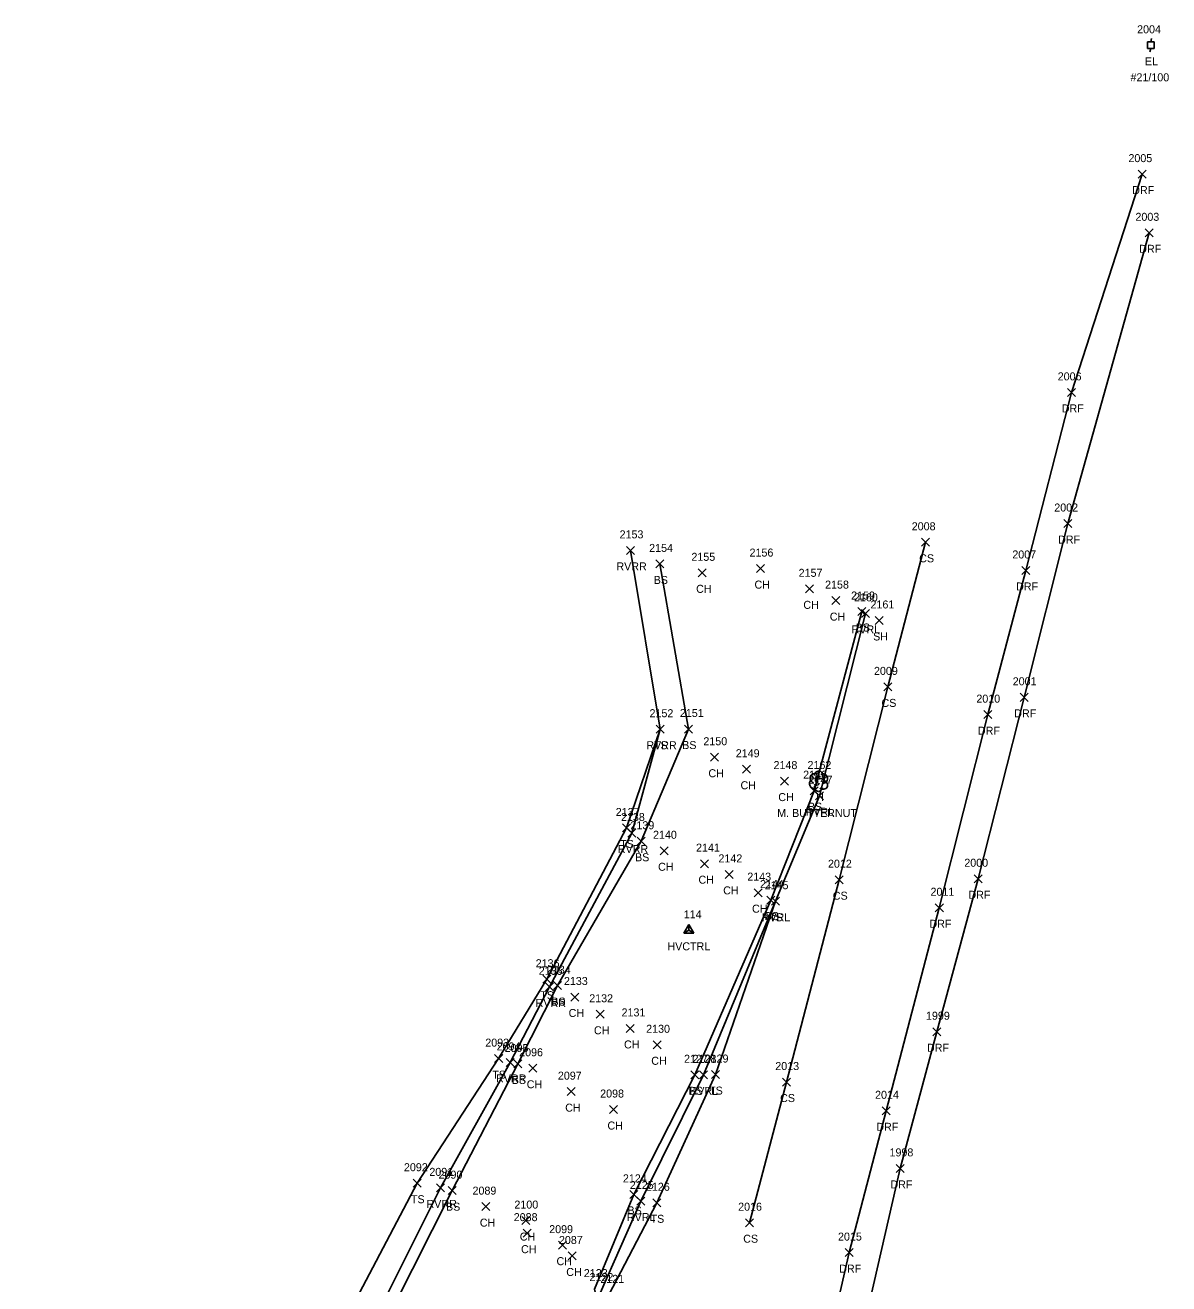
# Model space of a CAD drawing. Extents: x 1600395 to 1603269, y 874955 to 877143.
# Drawn here: x 1601782.9 to 1602068.5, y 875406.7 to 875721.2 of the extents above; entities that cross this region are included whole.
import ezdxf

# ---------------------------------------------------------------- set-up
doc = ezdxf.new("R2010")
doc.units = 0
for name, color, linetype in [('C_A', 7, 'Continuous'), ('C_I', 7, 'Continuous'), ('CPSM', 7, 'Continuous'), ('L_A', 7, 'Continuous'), ('L_C', 7, 'Continuous'), ('L_I', 7, 'Continuous'), ('L_TIC', 7, 'Continuous'), ('LAWE', 7, 'Continuous'), ('LELB', 7, 'Continuous'), ('LTD', 7, 'Continuous'), ('R_A', 7, 'Continuous'), ('R_I', 7, 'Continuous'), ('R_TIC', 7, 'Continuous'), ('RDF', 7, 'Continuous'), ('U_A', 7, 'Continuous'), ('U_C', 7, 'Continuous'), ('U_I', 7, 'Continuous'), ('UEPT', 7, 'Continuous')]:
    doc.layers.add(name, color=color, linetype=linetype)

msp = doc.modelspace()

# ---------------------------------------------------------------- linework, layer by layer
at = {"layer": 'CPSM'}
for p, q in [((1601947.35, 875494.34), (1601948.6, 875496.51)), ((1601949.85, 875494.34), (1601948.6, 875496.51)), ((1601948.6, 875495.06), (1601948.6, 875496.51)), ((1601947.35, 875494.34), (1601948.6, 875495.06)), ((1601947.35, 875494.34), (1601949.85, 875494.34)), ((1601948.6, 875495.06), (1601948.6, 875495.06)), ((1601948.6, 875495.06), (1601949.85, 875494.34))]:
    msp.add_line(p, q, dxfattribs=at)
at = {"layer": 'L_TIC'}
for points in [[(1601933.04, 875589), (1601935.04, 875591)], [(1601935.04, 875589), (1601933.04, 875591)], [(1602006.73, 875591.02), (1602008.73, 875593.02)], [(1602008.73, 875591.02), (1602006.73, 875593.02)], [(1601940.42, 875585.61), (1601942.42, 875587.61)], [(1601942.42, 875585.61), (1601940.42, 875587.61)], [(1601950.97, 875583.39), (1601952.97, 875585.39)], [(1601952.97, 875583.39), (1601950.97, 875585.39)], [(1601965.55, 875584.45), (1601967.55, 875586.45)], [(1601967.55, 875584.45), (1601965.55, 875586.45)], [(1601977.75, 875579.39), (1601979.75, 875581.39)], [(1601979.75, 875579.39), (1601977.75, 875581.39)], [(1601984.36, 875576.45), (1601986.36, 875578.45)], [(1601986.36, 875576.45), (1601984.36, 875578.45)], [(1601990.87, 875573.72), (1601992.87, 875575.72)], [(1601992.87, 875573.72), (1601990.87, 875575.72)], [(1601991.72, 875573.26), (1601993.72, 875575.26)], [(1601993.72, 875573.26), (1601991.72, 875575.26)], [(1601995.18, 875571.49), (1601997.18, 875573.49)], [(1601997.18, 875571.49), (1601995.18, 875573.49)], [(1601997.31, 875554.89), (1601999.31, 875556.89)], [(1601999.31, 875554.89), (1601997.31, 875556.89)], [(1601940.51, 875544.31), (1601942.51, 875546.31)], [(1601942.51, 875544.31), (1601940.51, 875546.31)], [(1601940.51, 875544.31), (1601942.51, 875546.31)], [(1601942.51, 875544.31), (1601940.51, 875546.31)], [(1601947.53, 875544.36), (1601949.53, 875546.36)], [(1601949.53, 875544.36), (1601947.53, 875546.36)], [(1601954.05, 875537.31), (1601956.05, 875539.31)], [(1601956.05, 875537.31), (1601954.05, 875539.31)], [(1601962.06, 875534.31), (1601964.06, 875536.31)], [(1601964.06, 875534.31), (1601962.06, 875536.31)], [(1601971.49, 875531.35), (1601973.49, 875533.35)], [(1601973.49, 875531.35), (1601971.49, 875533.35)], [(1601978.94, 875528.95), (1601980.94, 875530.95)], [(1601980.94, 875528.95), (1601978.94, 875530.95)], [(1601980.24, 875527.67), (1601982.24, 875529.67)], [(1601982.24, 875527.67), (1601980.24, 875529.67)], [(1601932.08, 875519.64), (1601934.08, 875521.64)], [(1601934.08, 875519.64), (1601932.08, 875521.64)], [(1601933.38, 875518.38), (1601935.38, 875520.38)], [(1601935.38, 875518.38), (1601933.38, 875520.38)], [(1601935.76, 875516.32), (1601937.76, 875518.32)], [(1601937.76, 875516.32), (1601935.76, 875518.32)], [(1601941.47, 875513.94), (1601943.47, 875515.94)], [(1601943.47, 875513.94), (1601941.47, 875515.94)], [(1601951.56, 875510.71), (1601953.56, 875512.71)], [(1601953.56, 875510.71), (1601951.56, 875512.71)], [(1601957.73, 875508.04), (1601959.73, 875510.04)], [(1601959.73, 875508.04), (1601957.73, 875510.04)], [(1601985.16, 875506.71), (1601987.16, 875508.71)], [(1601987.16, 875506.71), (1601985.16, 875508.71)], [(1601964.93, 875503.47), (1601966.93, 875505.47)], [(1601966.93, 875503.47), (1601964.93, 875505.47)], [(1601968.1, 875501.62), (1601970.1, 875503.62)], [(1601970.1, 875501.62), (1601968.1, 875503.62)], [(1601969.27, 875501.33), (1601971.27, 875503.33)], [(1601971.27, 875501.33), (1601969.27, 875503.33)], [(1601969.27, 875501.33), (1601971.27, 875503.33)], [(1601971.27, 875501.33), (1601969.27, 875503.33)], [(1601912.14, 875481.84), (1601914.14, 875483.84)], [(1601914.14, 875481.84), (1601912.14, 875483.84)], [(1601912.85, 875479.94), (1601914.85, 875481.94)], [(1601914.85, 875479.94), (1601912.85, 875481.94)], [(1601914.86, 875480.25), (1601916.86, 875482.25)], [(1601916.86, 875480.25), (1601914.86, 875482.25)], [(1601919.13, 875477.4), (1601921.13, 875479.4)], [(1601921.13, 875477.4), (1601919.13, 875479.4)], [(1601925.46, 875473.08), (1601927.46, 875475.08)], [(1601927.46, 875473.08), (1601925.46, 875475.08)], [(1601932.96, 875469.55), (1601934.96, 875471.55)], [(1601934.96, 875469.55), (1601932.96, 875471.55)], [(1601939.76, 875465.46), (1601941.76, 875467.46)], [(1601941.76, 875465.46), (1601939.76, 875467.46)], [(1601900.14, 875462), (1601902.14, 875464)], [(1601902.14, 875462), (1601900.14, 875464)], [(1601902.98, 875461.05), (1601904.98, 875463.05)], [(1601904.98, 875461.05), (1601902.98, 875463.05)], [(1601904.96, 875460.66), (1601906.96, 875462.66)], [(1601906.96, 875460.66), (1601904.96, 875462.66)], [(1601908.66, 875459.59), (1601910.66, 875461.59)], [(1601910.66, 875459.59), (1601908.66, 875461.59)], [(1601949.13, 875457.97), (1601951.13, 875459.97)], [(1601951.13, 875457.97), (1601949.13, 875459.97)], [(1601951.26, 875457.95), (1601953.26, 875459.95)], [(1601953.26, 875457.95), (1601951.26, 875459.95)], [(1601954.29, 875458.02), (1601956.29, 875460.02)], [(1601956.29, 875458.02), (1601954.29, 875460.02)], [(1601918.27, 875453.75), (1601920.27, 875455.75)], [(1601920.27, 875453.75), (1601918.27, 875455.75)], [(1601972, 875456.15), (1601974, 875458.15)], [(1601974, 875456.15), (1601972, 875458.15)], [(1601928.82, 875449.28), (1601930.82, 875451.28)], [(1601930.82, 875449.28), (1601928.82, 875451.28)], [(1601879.82, 875430.87), (1601881.82, 875432.87)], [(1601881.82, 875430.87), (1601879.82, 875432.87)], [(1601885.6, 875429.71), (1601887.6, 875431.71)], [(1601887.6, 875429.71), (1601885.6, 875431.71)], [(1601888.55, 875429.01), (1601890.55, 875431.01)], [(1601890.55, 875429.01), (1601888.55, 875431.01)], [(1601933.86, 875428.08), (1601935.86, 875430.08)], [(1601935.86, 875428.08), (1601933.86, 875430.08)], [(1601935.61, 875426.42), (1601937.61, 875428.42)], [(1601937.61, 875426.42), (1601935.61, 875428.42)], [(1601939.67, 875425.98), (1601941.67, 875427.98)], [(1601941.67, 875425.98), (1601939.67, 875427.98)], [(1601896.95, 875425.02), (1601898.95, 875427.02)], [(1601898.95, 875425.02), (1601896.95, 875427.02)], [(1601906.93, 875421.53), (1601908.93, 875423.53)], [(1601908.93, 875421.53), (1601906.93, 875423.53)], [(1601962.78, 875421), (1601964.78, 875423)], [(1601964.78, 875421), (1601962.78, 875423)], [(1601907.24, 875418.39), (1601909.24, 875420.39)], [(1601909.24, 875418.39), (1601907.24, 875420.39)], [(1601916.1, 875415.39), (1601918.1, 875417.39)], [(1601918.1, 875415.39), (1601916.1, 875417.39)], [(1601918.53, 875412.69), (1601920.53, 875414.69)], [(1601920.53, 875412.69), (1601918.53, 875414.69)]]:
    msp.add_lwpolyline(points, dxfattribs=at)
at = {"layer": 'LAWE'}
for points in [[(1601871.66, 875400.7), (1601886.6, 875430.71), (1601903.98, 875462.05), (1601913.85, 875480.94), (1601934.38, 875519.38), (1601941.51, 875545.31), (1601934.04, 875590)], [(1601926.51, 875404.41), (1601936.61, 875427.42), (1601952.26, 875458.95), (1601970.27, 875502.33), (1601981.24, 875528.67), (1601992.72, 875574.26)]]:
    msp.add_lwpolyline(points, dxfattribs=at)
at = {"layer": 'LELB'}
for points in [[(1602007.73, 875592.02), (1601998.31, 875555.89), (1601986.16, 875507.71), (1601973, 875457.15), (1601963.78, 875422)], [(1601782.88, 875259.7), (1601797.54, 875287.39), (1601818.14, 875317.83), (1601840.05, 875340.05), (1601859.67, 875369.32), (1601874.59, 875400.48), (1601889.55, 875430.01), (1601905.96, 875461.66), (1601915.86, 875481.25), (1601936.76, 875517.32), (1601948.53, 875545.36), (1601941.42, 875586.61)], [(1601870.72, 875282.07), (1601873.73, 875299.56), (1601885.11, 875329.71), (1601896.52, 875360.64), (1601915.58, 875394.32), (1601921.27, 875400.59), (1601925.94, 875399.76), (1601925.98, 875401.46), (1601925.1, 875405.41), (1601934.86, 875429.08), (1601950.13, 875458.97), (1601969.1, 875502.62), (1601979.94, 875529.95), (1601991.87, 875574.72)], [(1601864.61, 875401.11), (1601880.82, 875431.87), (1601901.14, 875463), (1601913.14, 875482.84), (1601933.08, 875520.64), (1601941.51, 875545.31)], [(1601928.66, 875403.97), (1601940.67, 875426.98), (1601955.29, 875459.02), (1601970.27, 875502.33)]]:
    msp.add_lwpolyline(points, dxfattribs=at)
at = {"layer": 'LTD'}
msp.add_line((1601981.02, 875532.37), (1601981.02, 875532.37), dxfattribs=at)
msp.add_line((1601981.02, 875532.37), (1601981.02, 875532.37), dxfattribs=at)
msp.add_arc((1601981.06, 875533.8), 1.05, 335.5272, 180.9563, dxfattribs=at)
for centre, major_axis, ratio, start_param, end_param in [((1601980.23, 875533.03), (1.21, -0.51), 0.895232, 1.570796, 4.712389), ((1601982.06, 875532.95), (-1.14, -0.48), 0.949671, 1.570796, 4.712389), ((1601979.93, 875531.66), (0.58, -1.04), 0.959034, 3.141593, 6.283185), ((1601981.02, 875530.87), (0.26, 1.06), 0.942809, 1.570796, 4.712389), ((1601980.56, 875531.62), (-0.625, -0.083), 0.423636, 0, 3.141593), ((1601980.81, 875532.83), (-0.208, -0.792), 0.645439, 3.141593, 6.283185), ((1601981.52, 875532.2), (-0.5, 0.667), 0.989748, 3.141593, 6.283185), ((1601982.02, 875531.53), (-1.09, 0.79), 0.841452, 1.570796, 4.712389)]:
    msp.add_ellipse(centre, major_axis=major_axis, ratio=ratio, start_param=start_param, end_param=end_param, dxfattribs=at)
at = {"layer": 'R_TIC'}
for points in [[(1602060.84, 875683.02), (1602062.84, 875685.02)], [(1602062.84, 875683.02), (1602060.84, 875685.02)], [(1602062.59, 875668.35), (1602064.59, 875670.35)], [(1602064.59, 875668.35), (1602062.59, 875670.35)], [(1602043.24, 875628.48), (1602045.24, 875630.48)], [(1602045.24, 875628.48), (1602043.24, 875630.48)], [(1602042.33, 875595.71), (1602044.33, 875597.71)], [(1602044.33, 875595.71), (1602042.33, 875597.71)], [(1602031.84, 875583.98), (1602033.84, 875585.98)], [(1602033.84, 875583.98), (1602031.84, 875585.98)], [(1602031.38, 875552.28), (1602033.38, 875554.28)], [(1602033.38, 875552.28), (1602031.38, 875554.28)], [(1602022.3, 875547.95), (1602024.3, 875549.95)], [(1602024.3, 875547.95), (1602022.3, 875549.95)], [(1602019.94, 875506.95), (1602021.94, 875508.95)], [(1602021.94, 875506.95), (1602019.94, 875508.95)], [(1602010.2, 875499.7), (1602012.2, 875501.7)], [(1602012.2, 875499.7), (1602010.2, 875501.7)], [(1602009.57, 875468.72), (1602011.57, 875470.72)], [(1602011.57, 875468.72), (1602009.57, 875470.72)], [(1601996.92, 875448.96), (1601998.92, 875450.96)], [(1601998.92, 875448.96), (1601996.92, 875450.96)], [(1602000.45, 875434.57), (1602002.45, 875436.57)], [(1602002.45, 875434.57), (1602000.45, 875436.57)], [(1601987.66, 875413.53), (1601989.66, 875415.53)], [(1601989.66, 875413.53), (1601987.66, 875415.53)]]:
    msp.add_lwpolyline(points, dxfattribs=at)
at = {"layer": 'RDF'}
for points in [[(1602061.84, 875684.02), (1602044.24, 875629.48), (1602032.84, 875584.98), (1602023.3, 875548.95), (1602011.2, 875500.7), (1601997.92, 875449.96), (1601988.66, 875414.53), (1601981.1, 875381.42), (1601975.47, 875363.36), (1601973.75, 875359.58), (1601972.05, 875352.54), (1601961.77, 875334.39), (1601952.58, 875318.57), (1601943.82, 875302.36), (1601937.98, 875289.88), (1601931.35, 875281.77)], [(1601949.48, 875279.46), (1601947.41, 875284.4), (1601949.28, 875291.02), (1601956.31, 875304.78), (1601960.93, 875313.4), (1601971.12, 875331.84), (1601980.7, 875349.27), (1601982.5, 875352.91), (1601983.72, 875356.75), (1601986.1, 875362.37), (1601988.2, 875377.06), (1601992.91, 875398.51), (1602001.45, 875435.57), (1602010.57, 875469.72), (1602020.94, 875507.95), (1602032.38, 875553.28), (1602043.33, 875596.71), (1602063.59, 875669.35)]]:
    msp.add_lwpolyline(points, dxfattribs=at)
at = {"layer": 'UEPT'}
for p, q in [((1602063.18, 875715.37), (1602063.18, 875717.04)), ((1602063.18, 875717.04), (1602064.85, 875717.04)), ((1602064.18, 875717.87), (1602064.02, 875717.04)), ((1602064.85, 875717.04), (1602064.85, 875715.37)), ((1602064.85, 875715.37), (1602063.18, 875715.37)), ((1602063.77, 875714.54), (1602064.02, 875715.37)), ((1602064.02, 875716.21), (1602064.02, 875716.21))]:
    msp.add_line(p, q, dxfattribs=at)

# ---------------------------------------------------------------- texts
at = {"layer": 'C_A'}
msp.add_text('HVCTRL', height=2, dxfattribs=at).set_placement((1601943.29, 875490.06))
at = {"layer": 'C_I'}
msp.add_text('114', height=2, dxfattribs=at).set_placement((1601947.37, 875498.06))
at = {"layer": 'L_A'}
for s, p in [('CS', (1602006.17, 875587.02)), ('RVRR', (1601930.55, 875585)), ('BS', (1601939.86, 875581.61)), ('CH', (1601950.46, 875579.39)), ('CH', (1601965.04, 875580.45)), ('CH', (1601977.24, 875575.39)), ('CH', (1601983.85, 875572.45)), ('RVRL', (1601989.29, 875569.26)), ('BS', (1601990.31, 875569.72)), ('SH', (1601994.67, 875567.49)), ('CS', (1601996.75, 875550.89)), ('RVRR', (1601938.03, 875540.31)), ('TS', (1601939.92, 875540.31)), ('BS', (1601946.97, 875540.36)), ('CH', (1601953.53, 875533.31)), ('CH', (1601961.55, 875530.31)), ('CH', (1601970.98, 875527.35)), ('H', (1601980.45, 875527.37)), ('RVRL', (1601977.81, 875523.67)), ('BS', (1601978.38, 875524.95)), ('RVRR', (1601930.9, 875514.38)), ('TS', (1601931.49, 875515.64)), ('BS', (1601935.2, 875512.32)), ('CH', (1601940.96, 875509.94)), ('CH', (1601951.05, 875506.71)), ('CH', (1601957.22, 875504.04)), ('CS', (1601984.6, 875502.71)), ('CH', (1601964.42, 875499.47)), ('BS', (1601967.54, 875497.62)), ('RVRL', (1601966.83, 875497.33)), ('TS', (1601968.68, 875497.33)), ('RVRR', (1601910.36, 875475.94)), ('TS', (1601911.55, 875477.84)), ('BS', (1601914.3, 875476.25)), ('CH', (1601918.62, 875473.4)), ('CH', (1601924.94, 875469.08)), ('CH', (1601932.45, 875465.55)), ('CH', (1601939.25, 875461.46)), ('TS', (1601899.55, 875458)), ('RVRR', (1601900.49, 875457.05)), ('BS', (1601904.41, 875456.66)), ('CH', (1601908.15, 875455.59)), ('BS', (1601948.57, 875453.97)), ('RVRL', (1601948.83, 875453.95)), ('TS', (1601953.7, 875454.02)), ('CS', (1601971.44, 875452.15)), ('CH', (1601917.76, 875449.75)), ('CH', (1601928.31, 875445.28)), ('TS', (1601879.23, 875426.87)), ('RVRR', (1601883.11, 875425.71)), ('BS', (1601887.99, 875425.01)), ('RVRL', (1601933.17, 875422.42)), ('BS', (1601933.3, 875424.08)), ('CH', (1601896.44, 875421.02)), ('TS', (1601939.08, 875421.98)), ('CH', (1601906.42, 875417.53)), ('CS', (1601962.22, 875417)), ('CH', (1601906.73, 875414.39)), ('CH', (1601915.59, 875411.39)), ('CH', (1601918.02, 875408.69))]:
    msp.add_text(s, height=2, dxfattribs=at).set_placement(p)
at = {"layer": 'L_C'}
msp.add_text('M. BUTTERNUT', height=2, dxfattribs=at).set_placement((1601970.71, 875523.37))
at = {"layer": 'L_I'}
for s, p in [('2008', (1602004.31, 875595.02)), ('2153', (1601931.34, 875593)), ('2154', (1601938.73, 875589.61)), ('2155', (1601949.28, 875587.39)), ('2156', (1601963.8, 875588.45)), ('2157', (1601976.06, 875583.39)), ('2158', (1601982.67, 875580.45)), ('2159', (1601989.17, 875577.72)), ('2160', (1601989.89, 875577.26)), ('2161', (1601994.01, 875575.49)), ('2009', (1601994.88, 875558.89)), ('2152', (1601938.82, 875548.31)), ('2152', (1601938.82, 875548.31)), ('2151', (1601946.4, 875548.36)), ('2150', (1601952.27, 875541.31)), ('2149', (1601960.36, 875538.31)), ('2148', (1601969.79, 875535.35)), ('2162', (1601978.28, 875535.37)), ('2146', (1601977.19, 875532.95)), ('2147', (1601978.55, 875531.67)), ('2137', (1601930.38, 875523.64)), ('2138', (1601931.69, 875522.38)), ('2139', (1601934.06, 875520.32)), ('2140', (1601939.69, 875517.94)), ('2141', (1601950.43, 875514.71)), ('2142', (1601956.03, 875512.04)), ('2012', (1601983.39, 875510.71)), ('2143', (1601963.24, 875507.47)), ('2144', (1601966.41, 875505.62)), ('2145', (1601967.57, 875505.33)), ('2145', (1601967.57, 875505.33)), ('2136', (1601910.39, 875485.84)), ('2135', (1601911.15, 875483.94)), ('2134', (1601913.17, 875484.25)), ('2133', (1601917.44, 875481.4)), ('2132', (1601923.76, 875477.08)), ('2131', (1601931.83, 875473.55)), ('2130', (1601937.98, 875469.46)), ('2093', (1601897.8, 875466)), ('2094', (1601900.64, 875465.05)), ('2095', (1601902.63, 875464.66)), ('2096', (1601906.26, 875463.59)), ('2127', (1601947.44, 875461.97)), ('2128', (1601949.57, 875461.95)), ('2129', (1601952.59, 875462.02)), ('2013', (1601970.23, 875460.15)), ('2097', (1601915.93, 875457.75)), ('2098', (1601926.49, 875453.28)), ('2092', (1601877.48, 875434.87)), ('2091', (1601883.83, 875433.71)), ('2090', (1601886.13, 875433.01)), ('2124', (1601932.17, 875432.08)), ('2089', (1601894.61, 875429.02)), ('2125', (1601933.91, 875430.42)), ('2126', (1601937.92, 875429.98)), ('2100', (1601905.07, 875425.53)), ('2088', (1601904.9, 875422.39)), ('2016', (1601960.95, 875425)), ('2099', (1601913.76, 875419.39)), ('2087', (1601916.19, 875416.69)), ('2123', (1601922.41, 875408.41)), ('2122', (1601923.82, 875407.41)), ('2121', (1601926.53, 875406.97)), ('2121', (1601926.53, 875406.97))]:
    msp.add_text(s, height=2, dxfattribs=at).set_placement(p)
at = {"layer": 'R_A'}
for p in [(1602059.38, 875679.02), (1602061.13, 875664.35), (1602041.78, 875624.48), (1602040.86, 875591.71), (1602030.38, 875579.98), (1602029.92, 875548.28), (1602020.84, 875543.95), (1602018.48, 875502.95), (1602008.74, 875495.7), (1602008.11, 875464.72), (1601995.46, 875444.96), (1601998.98, 875430.57), (1601986.2, 875409.53)]:
    msp.add_text('DRF', height=2, dxfattribs=at).set_placement(p)
at = {"layer": 'R_I'}
for s, p in [('2005', (1602058.43, 875687.02)), ('2003', (1602060.18, 875672.35)), ('2006', (1602040.77, 875632.48)), ('2002', (1602039.91, 875599.71)), ('2007', (1602029.43, 875587.98)), ('2001', (1602029.53, 875556.28)), ('2010', (1602020.45, 875551.95)), ('2000', (1602017.44, 875510.95)), ('2011', (1602009, 875503.7)), ('1999', (1602007.87, 875472.72)), ('2014', (1601995.15, 875452.96)), ('1998', (1601998.76, 875438.57)), ('2015', (1601985.89, 875417.53))]:
    msp.add_text(s, height=2, dxfattribs=at).set_placement(p)
at = {"layer": 'U_A'}
msp.add_text('EL', height=2, dxfattribs=at).set_placement((1602062.55, 875711.21))
at = {"layer": 'U_C'}
msp.add_text('#21/100', height=2, dxfattribs=at).set_placement((1602058.95, 875707.21))
at = {"layer": 'U_I'}
msp.add_text('2004', height=2, dxfattribs=at).set_placement((1602060.6, 875719.21))

doc.saveas('drawing.dxf')
